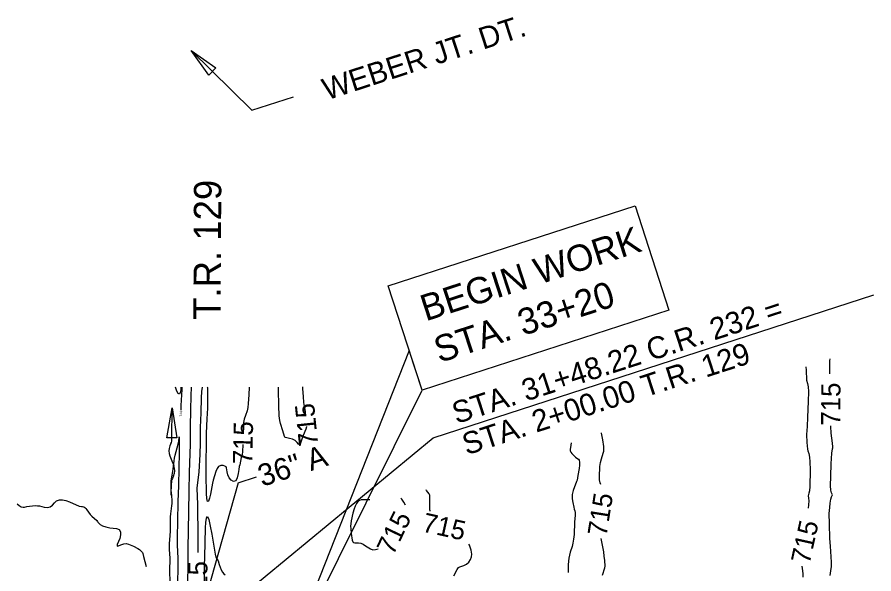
# Model space of a CAD drawing. Extents: x -468563856 to 36492962, y -306094093 to 11899197.
# Drawn here: x 1821466 to 1822934, y 531615 to 532569 of the extents above; entities that cross this region are included whole.
import ezdxf

# ---------------------------------------------------------------- set-up
doc = ezdxf.new("R2010")
doc.units = 0
for name, color, linetype in [('DT_X_Contour_Minor', 7, 'Continuous'), ('Level 19', 7, 'Continuous'), ('Level 31', 7, 'Continuous'), ('Level 40', 7, 'Continuous'), ('SH_Text', 7, 'Continuous')]:
    doc.layers.add(name, color=color, linetype=linetype)

msp = doc.modelspace()

# ---------------------------------------------------------------- linework, layer by layer
at = {"layer": 'DT_X_Contour_Minor'}
for points in [[(1822858.6, 531957.7), (1822858.5, 531962), (1822858.5, 531980), (1822858.7, 531983.2)], [(1822817.5, 531969.8), (1822817.9, 531963.8), (1822818.4, 531946.7), (1822820.4, 531940.9), (1822821.3, 531935.5), (1822821.7, 531927.4), (1822821.4, 531910.3), (1822820.2, 531883), (1822819.6, 531867.5), (1822818.7, 531853.6), (1822819.2, 531840), (1822820.2, 531828.6), (1822820.7, 531825.3), (1822822.2, 531821), (1822823.1, 531818.3), (1822823.8, 531813.9), (1822824.4, 531807), (1822824.8, 531792.4), (1822824.1, 531764.2), (1822823.5, 531757.2), (1822822.6, 531752.7), (1822821.1, 531748.6), (1822822.1, 531744.3), (1822822.4, 531739.8), (1822821.9, 531733), (1822821.2, 531727.5)], [(1821746.8, 531934.7), (1821746.6, 531930.2), (1821745.8, 531925.5), (1821744.5, 531922.9), (1821742.4, 531924.1), (1821740, 531927.8), (1821737.9, 531932.7), (1821737.3, 531934.7)], [(1821747.1, 531895.5), (1821747.4, 531903.3), (1821749, 531930.7), (1821749.1, 531934.7)], [(1821758.9, 531598.7), (1821759.2, 531630.8), (1821759.5, 531659.1), (1821759.8, 531688.3), (1821760.3, 531722.2), (1821761.1, 531755.9), (1821761.4, 531788.9), (1821762.6, 531820.6), (1821763.1, 531836.8), (1821763.4, 531866.9), (1821763.8, 531896), (1821764.5, 531920.1), (1821765, 531934.7)], [(1821783, 531934.8), (1821782.3, 531927.3), (1821781.7, 531916.3), (1821781, 531890.6), (1821780.1, 531865.3), (1821779.9, 531839.1), (1821779.1, 531819.2), (1821777.5, 531789.5), (1821774.4, 531761.3), (1821775.3, 531733.5), (1821775.5, 531720), (1821775.7, 531690.5), (1821775.7, 531667.4), (1821775.6, 531651.4)], [(1821853, 531836.6), (1821852.5, 531823.6), (1821851.6, 531819.3), (1821850.1, 531814), (1821847.5, 531801.3), (1821846.7, 531798.5), (1821845.9, 531793.8), (1821844.9, 531786.8), (1821843.3, 531779.3), (1821840.7, 531773.9), (1821837, 531772.7), (1821832.9, 531775), (1821829.3, 531779.4), (1821827, 531784.5), (1821825.8, 531789.6), (1821824.9, 531796.6), (1821824.1, 531798.3), (1821822.3, 531799.4), (1821819.1, 531800.2), (1821815.2, 531800.3), (1821811.5, 531798.7), (1821808.7, 531795), (1821806.6, 531790), (1821802.3, 531775.2), (1821801.1, 531770.3), (1821797.5, 531751.2), (1821795.7, 531744.1), (1821793.9, 531739.1), (1821792.3, 531738.5), (1821791.3, 531743.9), (1821790.8, 531752.6), (1821790.3, 531784.2), (1821790.1, 531807.4), (1821790.4, 531835.8), (1821790.7, 531855.6), (1821792.1, 531880.6), (1821793, 531898.6), (1821793.1, 531915.5), (1821793.1, 531928.6), (1821792.7, 531933.7), (1821792.4, 531934.8)], [(1821864, 531934.9), (1821863.4, 531921.3), (1821862.3, 531906.6), (1821861.4, 531899.8), (1821860.3, 531894.3), (1821857.7, 531886.3), (1821855.4, 531879.8), (1821854.6, 531877), (1821854.1, 531874.2), (1821853.8, 531867.2), (1821853.5, 531854.6)], [(1821961.7, 531867.3), (1821961.7, 531866.9), (1821960.9, 531862.8), (1821959.3, 531858.5), (1821955.1, 531848.8), (1821951.6, 531838.4), (1821950, 531835.9), (1821948.3, 531836.8), (1821946, 531839.8), (1821942.6, 531843.1), (1821937.8, 531845.5), (1821932.6, 531846.9), (1821925.8, 531848.6), (1821924.8, 531849.2), (1821924.4, 531850.3), (1821921.2, 531859.8), (1821917.2, 531872.5), (1821916.1, 531877.5), (1821915.4, 531885.5), (1821914.4, 531903.3), (1821914.1, 531929.5), (1821913.9, 531934.9)], [(1821955.1, 531935), (1821955.3, 531932), (1821956, 531918.9), (1821956.6, 531908.2), (1821957.2, 531904.7), (1821958.7, 531899.4), (1821959.6, 531893.1), (1821960.5, 531885.2)], [(1822466.2, 531767.6), (1822465.1, 531770.9), (1822464.1, 531775.9), (1822463.9, 531780.7), (1822464.7, 531798.9), (1822465.6, 531805.6), (1822467.1, 531811.7), (1822470.3, 531821.4), (1822471.2, 531825), (1822471.3, 531828.6), (1822471, 531832.9), (1822469.3, 531844.4), (1822467.4, 531855.9), (1822467.4, 531856.2)], [(1822858.8, 531611.9), (1822860.9, 531623.7), (1822861.3, 531626.5), (1822861, 531634.9), (1822859.4, 531662.3), (1822858.3, 531675.3), (1822857.7, 531700.3), (1822857.5, 531717.9), (1822858.3, 531728.2), (1822859, 531735.8), (1822860.2, 531742.5), (1822861.5, 531746.7), (1822863.1, 531750.1), (1822861.1, 531753.4), (1822860, 531758), (1822859.6, 531765.6), (1822860.2, 531782), (1822860.8, 531803.5), (1822861.8, 531821.3), (1822862.9, 531828.9), (1822863.3, 531830.5), (1822863.4, 531832.2), (1822862.8, 531838.4), (1822860.7, 531855.8), (1822860, 531867), (1822860, 531868.5)], [(1821728.2, 531600.1), (1821727.9, 531619.8), (1821728.4, 531641.1), (1821727.9, 531649.3), (1821727.4, 531656), (1821727.5, 531666.8), (1821728.4, 531679.8), (1821728.9, 531688.6), (1821729.1, 531700.6), (1821729.2, 531712.5), (1821729.5, 531717.8), (1821730.8, 531726.8), (1821731.5, 531731), (1821731.8, 531735.4), (1821731.9, 531740), (1821731.2, 531748.7), (1821730.2, 531757.9), (1821730, 531763.2), (1821730, 531768.7), (1821730.3, 531774.1), (1821731.9, 531783.9), (1821733.7, 531794), (1821735.4, 531808.4), (1821735.9, 531812.7), (1821736.9, 531817.9), (1821740.3, 531830.8), (1821743.1, 531841.3), (1821743.9, 531849.4), (1821743.7, 531822.1), (1821743.3, 531795.8), (1821742.7, 531766.3), (1821741.6, 531737.9), (1821740.8, 531705.1), (1821740.5, 531677.5), (1821740.7, 531664.4), (1821741.5, 531640.8), (1821741.4, 531622.8), (1821741.2, 531602.3)], [(1822415.2, 531839.3), (1822414.2, 531831.5), (1822413.5, 531828.3), (1822413.5, 531825.5), (1822414.6, 531823.1), (1822416.4, 531820.9), (1822422.9, 531814.6), (1822424.8, 531813.1), (1822428, 531811.5), (1822429, 531809.6), (1822429.5, 531806.1), (1822429.4, 531801.2), (1822428.8, 531795.4), (1822427, 531783.3), (1822425.4, 531775.4), (1822424.7, 531772.8), (1822418.5, 531757.6), (1822417, 531750.4), (1822417, 531743.4), (1822418.1, 531737.1), (1822419.9, 531728.8), (1822420.3, 531725.4), (1822421.7, 531722.8), (1822422.1, 531719.8), (1822421.9, 531715), (1822420.9, 531703.4), (1822420.2, 531682), (1822419.4, 531674.3), (1822418.2, 531667.1), (1822416.8, 531661.4), (1822413.6, 531652), (1822412.3, 531646.9), (1822411.3, 531641.4), (1822410.2, 531630.7), (1822410, 531620.6), (1822410.2, 531616.9)], [(1822174, 531722.1), (1822173.6, 531723), (1822173.3, 531723.9), (1822173.2, 531728.6), (1822173.2, 531749.4), (1822172.8, 531750.5), (1822172, 531751.9), (1822167.8, 531757.5), (1822167, 531758.5)], [(1821466.3, 531734.6), (1821469.6, 531731.9), (1821473.4, 531729.6), (1821476.4, 531728.8), (1821479.2, 531729.1), (1821482.7, 531730), (1821487.5, 531730.8), (1821492.8, 531731.4), (1821497.7, 531731.6), (1821501.3, 531731.5), (1821504.4, 531731), (1821512.7, 531729), (1821518.1, 531728.4), (1821523, 531729.4), (1821526.9, 531732.4), (1821530.3, 531736.3), (1821534, 531739.7), (1821538.7, 531741.3), (1821544.2, 531741.3), (1821550, 531740.1), (1821555.8, 531738.1), (1821572.4, 531730.9), (1821576.6, 531730.1), (1821578.5, 531729.9), (1821580.3, 531729.3), (1821582.2, 531728.2), (1821584, 531726.5), (1821585.8, 531724.3), (1821591.5, 531716.1), (1821594, 531713.5), (1821602.9, 531706), (1821604, 531704.5), (1821604.8, 531703), (1821606, 531701.4), (1821608.5, 531699.4), (1821612.8, 531697.1), (1821618.5, 531695), (1821624.9, 531693.5), (1821636.8, 531692.3), (1821640.9, 531690.5), (1821643.1, 531686.7), (1821643.4, 531681.3), (1821642.2, 531675.3), (1821637.8, 531664.8), (1821637.4, 531662.3), (1821639.8, 531662.6), (1821644, 531664.4), (1821648.9, 531666.2), (1821653.2, 531666.5), (1821657.2, 531665.6), (1821665.5, 531662), (1821673.2, 531658.1), (1821675.8, 531656.5), (1821678.7, 531653.8), (1821680.9, 531651.1), (1821681.7, 531649.3), (1821682.9, 531644.3), (1821684.9, 531636), (1821687.2, 531627)], [(1822070.3, 531741.4), (1822069.2, 531741.3), (1822055.8, 531741.4), (1822052.8, 531740.6), (1822050.1, 531738.6), (1822047.6, 531735), (1822045.3, 531730.6), (1822043.5, 531726.1), (1822041.2, 531718.4), (1822038.5, 531705.3), (1822037.8, 531700.6), (1822037.6, 531696.1), (1822037.7, 531691.9), (1822038.7, 531683.6), (1822040.4, 531672.3), (1822041.1, 531669.7), (1822042.4, 531668.2), (1822044.5, 531667.8), (1822047.3, 531668), (1822050.8, 531668), (1822054.8, 531667.1), (1822059, 531665.3), (1822063.3, 531662.9), (1822071.4, 531657.4), (1822075.7, 531655.9), (1822080.3, 531656.1), (1822084.6, 531657.3)], [(1822131.4, 531732.1), (1822128.5, 531737.7), (1822125.3, 531742.5), (1822123.7, 531744.3)], [(1821787.2, 531596.4), (1821787.5, 531628), (1821787.7, 531644.3), (1821788.5, 531668), (1821789.2, 531693.6), (1821789.8, 531702.4), (1821790.8, 531710.3), (1821792.3, 531713), (1821794.6, 531707.7), (1821797.2, 531696.3), (1821799.7, 531682.4), (1821805.5, 531648.4), (1821806.9, 531643.2), (1821808.3, 531640.4), (1821810.4, 531636.9), (1821812.5, 531630.8), (1821816, 531621.4), (1821818.2, 531617.4), (1821820.4, 531614.8), (1821822.6, 531613)], [(1822240, 531634.8), (1822242.8, 531639.1), (1822244.4, 531643.9), (1822245, 531648.3), (1822244.7, 531652), (1822243.8, 531655.3), (1822240.9, 531663.6), (1822240.3, 531665.5)], [(1822469.1, 531612.2), (1822473.1, 531625.1), (1822473.4, 531627.8), (1822472.8, 531637.4), (1822472.1, 531644.7), (1822471, 531652.3), (1822467.1, 531672.3), (1822466.8, 531675.1)], [(1822214.1, 531611), (1822219.8, 531622.1), (1822221.1, 531624), (1822222.5, 531625.4), (1822224.4, 531626.5), (1822231.3, 531629.2), (1822235.9, 531631.5), (1822240, 531634.8)], [(1822810.4, 531627.8), (1822811.5, 531620), (1822812, 531614.6), (1822812.2, 531609.2)]]:
    msp.add_lwpolyline(points, dxfattribs=at)
at = {"layer": 'Level 31'}
for p, q in [((1821722.9, 531847.9), (1821731.8, 531899.5)), ((1821731.5, 531846.5), (1821731.8, 531899.5)), ((1821731.8, 531899.5), (1821740, 531847.8)), ((1821740, 531847.8), (1821722.9, 531847.9)), ((1821729.7, 531838), (1821728, 531833.9)), ((1821727.9, 531816.8), (1821731.4, 531808.1)), ((1821731.4, 531808.1), (1821734.6, 531800.5)), ((1821734.2, 531782.6), (1821732.2, 531778.3)), ((1821730.3, 531749.5), (1821730.5, 531770.4))]:
    msp.add_line(p, q, dxfattribs=at)
for centre, radius, start, end in [((1821709.1, 531846.6), 22.4, 337.3227, 359.6827), ((1821748.7, 531825.2), 22.4, 157.2839, 202.1277), ((1821713.8, 531792), 22.4, 335.15, 22.2585), ((1821749.7, 531770.3), 19.2, 155.1999, 179.6827)]:
    msp.add_arc(centre, radius, start, end, dxfattribs=at)
at = {"layer": 'Level 40'}
for p, q in [((1821794.8, 532469.7), (1821764.2, 532512.1)), ((1821764.2, 532512.1), (1821806.9, 532481.9)), ((1821806.9, 532481.9), (1821794.8, 532469.7)), ((1822179.2, 531848.1), (1822933.8, 532093.1)), ((1821765.8, 531506.7), (1822179.2, 531848.1)), ((1821844.7, 531770.5), (1821876.4, 531780.8)), ((1821844.7, 531770.5), (1821783.2, 531551.1))]:
    msp.add_line(p, q, dxfattribs=at)
msp.add_lwpolyline([(1821764.2, 532512.1), (1821868.2, 532409.3), (1821939.6, 532432.5)], dxfattribs=at)
at = {"layer": 'SH_Text'}
for points in [[(1822582.8, 532066.6), (1822160, 531929.3), (1822101.9, 532108.2), (1822524.8, 532245.5)], [(1822137.9, 531997.4), (1821920.9, 531447.8), (1822160, 531929.3)]]:
    msp.add_lwpolyline(points, close=True, dxfattribs=at)

# ---------------------------------------------------------------- texts
at = {"layer": 'Level 19'}
for s, height, rotation, p in [('715', 33, 89.771, (1822876.4, 531868.8)), ('715', 33, 95.9819, (1821982.3, 531835.2)), ('714', 4, 87.8917, (1821748.7, 531884.2)), ('715', 33, 88.6308, (1821868.8, 531802.2)), ('715', 33, 80.9589, (1822475.7, 531677.7)), ('715', 33, 64.1655, (1822110.4, 531645)), ('715', 33, 347.5104, (1822158.5, 531687.5)), ('715', 33, 77.5498, (1822823.6, 531630.2)), ('715', 33, 89.6049, (1821791.8, 531562.8))]:
    msp.add_text(s, height=height, rotation=rotation, dxfattribs=at).set_placement(p)
at = {"layer": 'Level 40'}
for s, height, rotation, p in [('WEBER JT. DT.', 37.5, 17.9864, (1821996.7, 532426.2)), ('T.R. 129', 46.8, 89.7137, (1821814.9, 532050.1)), ('STA. 31+48.22 C.R. 232 =', 37.5, 17.9864, (1822218.8, 531871.3)), ('STA. 2+00.00 T.R. 129', 37.5, 17.9864, (1822236.2, 531817.8)), ('36" A', 37.5, 17.9864, (1821886.1, 531763.6))]:
    msp.add_text(s, height=height, rotation=rotation, dxfattribs=at).set_placement(p)
at = {"layer": 'SH_Text'}
for s, p in [('BEGIN WORK', (1822166.2, 532047.3)), ('STA. 33+20', (1822189.4, 531975.9))]:
    msp.add_text(s, height=45.07, rotation=17.9864, dxfattribs=at).set_placement(p)

doc.saveas('drawing.dxf')
